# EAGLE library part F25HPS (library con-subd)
SUB-D
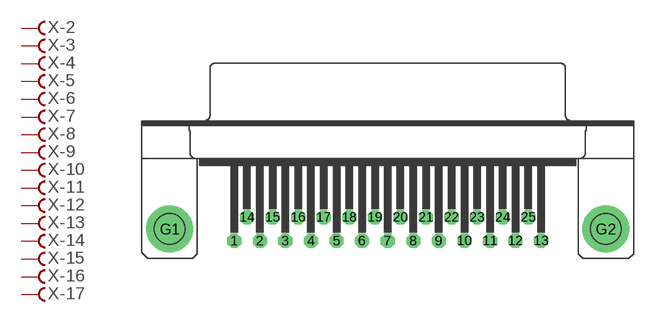
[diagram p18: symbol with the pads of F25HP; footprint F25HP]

Designator prefix X; gates -2=F -3=F -4=F -5=F -6=F -7=F -8=F -9=F -10=F -11=F -12=F -13=F -14=F -15=F -16=F -17=F -18=F -19=F -20=F -21=F -22=F -23=F -24=F -25=F -G=GND -1=FV

## F25HPS (OC_FARNELL: unknown; OC_NEWARK: unknown)  [F25HP]
1  -1:F  pas
2  -2:F  pas
3  -3:F  pas
4  -4:F  pas
5  -5:F  pas
6  -6:F  pas
7  -7:F  pas
8  -8:F  pas
9  -9:F  pas
10  -10:F  pas
11  -11:F  pas
12  -12:F  pas
13  -13:F  pas
14  -14:F  pas
15  -15:F  pas
16  -16:F  pas
17  -17:F  pas
18  -18:F  pas
19  -19:F  pas
20  -20:F  pas
21  -21:F  pas
22  -22:F  pas
23  -23:F  pas
24  -24:F  pas
25  -25:F  pas
G1  -G:G1  pas
G2  -G:G2  pas

## Footprint F25HP (pad centres in mm)
SUB-D
drill 1.016 octagon: 1 -16.561,-1.27; 2 -13.792,-1.27; 3 -11.049,-1.27; 4 -8.28,-1.27; 5 -5.512,-1.27; 6 -2.769,-1.27; 7 0,-1.27; 8 2.769,-1.27; 9 5.512,-1.27; 10 8.28,-1.27; 11 11.049,-1.27; 12 13.792,-1.27; 13 16.561,-1.27; 14 -15.189,1.27; 15 -12.421,1.27; 16 -9.652,1.27; 17 -6.909,1.27; 18 -4.14,1.27; 19 -1.372,1.27; 20 1.372,1.27; 21 4.14,1.27; 22 6.909,1.27; 23 9.652,1.27; 24 12.421,1.27; 25 15.189,1.27
drill 3.302 pad 5.08 round: G1 -23.52,0; G2 23.52,0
